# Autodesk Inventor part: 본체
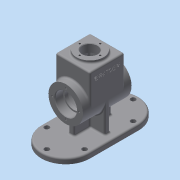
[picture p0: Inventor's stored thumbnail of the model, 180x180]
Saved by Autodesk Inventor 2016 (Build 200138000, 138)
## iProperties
Created: 2019-01
Part Number: 본체
Material: 알루미늄 6061
Document SubType Name: Modeling
Designer: mduedu
Density: 2.71 g/cm^3
Appearance: 기본값
Mass: 1057.72 g
Surface Area: 916.19 cm^2
Volume: 390.301 cm^3
Author: mduedu
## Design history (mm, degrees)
sketch "스케치1"
  geometry: C1 r 32 at (0, 0); 1 further point
  constraints: 1 centre point, 1 coincident
  dimensions: "d0" = 64 diameter of C1
extrude "돌출1" new body sketch "스케치1" stored distance "d1" = 90; taper "d2" = 0 deg
sketch "스케치2"
  geometry: L1 (0, 32)-(60, 32); L2 (60, 32)-(60, -32); L3 (60, -32)-(0, -32); L4 (0, -32)-(0, 32); C1 r 32 at (0, 0) reference; 2 further points
  constraints: 8 end point, 2 parallel, 1 coincident, 1 horizontal, 1 midpoint, 1 perpendicular, 1 tangent
  dimensions: "d5" = 60 distance between parallel lines of L4 L2
extrude "돌출2" join sketch "스케치2" stored distance "d7" = 64; taper "d8" = 0 deg
sketch "스케치3"
  geometry: C1 r 25 at (32, 32); 1 further point
  constraints: 1 centre point, 1 coincident
  dimensions: "d9" = 50 diameter of C1
extrude "돌출3" join sketch "스케치3" distance "d10" = 5; taper "d11" = 0 deg
sketch "스케치4"
  geometry: L1 (50, 25)-(0, 25); L2 (0, 25)-(0, -25); L3 (0, -25)-(50, -25); L4 (50, -25)-(50, 25); L5 (65, -25)-(65, 25) reference; A1 r 25 centre (0, 0) between (0, 25) and (0, -25); A2 r 25 centre (0, 0) between (0, -25) and (0, 25); 2 further points
  constraints: 8 end point, 4 point on circle, 2 centre point, 2 coincident, 2 parallel, 1 horizontal, 1 midpoint, 1 perpendicular, 1 tangent
  dimensions: "d12" = 50 diameter of A1; "d13" = 15 distance between parallel lines of L4 L5
extrude "돌출4" cut sketch "스케치4" stored distance "d14" = 48; taper "d15" = 0 deg
sketch "스케치5"
  geometry: C1 r 20 at (0, 0); 1 further point
  constraints: 1 centre point, 1 coincident
  dimensions: "d16" = 40 diameter of C1
extrude "돌출5" cut sketch "스케치5" distance "d17" = 15; taper "d18" = 0 deg
sketch "스케치6"
  geometry: C1 r 17 at (0, 0); 1 further point
  constraints: 1 centre point, 1 coincident
  dimensions: "d19" = 34 diameter of C1
extrude "돌출6" cut sketch "스케치6" stored distance "d20" = 15; taper "d21" = 0 deg
fillet "모깎기1" dims "d22" = 0.3
fillet "모깎기2" dims "d23" = 3
fillet "모깎기3" dims "d24" = 3
fillet "모깎기4" dims "d25" = 3
fillet "모깎기5" dims "d26" = 3
fillet "모깎기6" dims "d27" = 3
sketch "스케치7"
  geometry: C1 r 14 at (0, 0); 1 further point
  constraints: 1 centre point, 1 coincident
  dimensions: "d28" = 28 diameter of C1
extrude "돌출7" cut sketch "스케치7" stored distance "d29" = 15; taper "d30" = 0 deg
chamfer "모따기1" distance "d31" = 1; stored, may be unused: second distance "d32" = 2, angle "d33" = 45 deg
chamfer "모따기2" distance "d34" = 1; stored, may be unused: second distance "d35" = 2, angle "d36" = 45 deg
node "작업 평면1"
sketch "스케치8"
  geometry: L1 (45, 45)-(-45, 45); L2 (-45, 45)-(-45, -45); L3 (-45, -45)-(45, -45); L4 (45, -45)-(45, 45); L5 (45, 45)-(-45, -45); L6 (-45, 45)-(45, -45); A1 r 45 centre (45, 0) between (45, -45) and (45, 45); A2 r 45 centre (-45, 0) between (-45, 45) and (-45, -45); A3 r 45 centre (45, 0) between (0, 0) and (45, -45); A4 r 45 centre (45, 0) between (0, 0) and (0, 0); A5 r 45 centre (45, 0) between (45, 45) and (0, 0); A6 r 45 centre (-45, 0) between (0, 0) and (-45, 45); A7 r 45 centre (-45, 0) between (-45, -45) and (0, 0); 1 further point
  constraints: 14 point on circle, 12 end point, 7 centre point, 7 midpoint, 2 parallel, 1 horizontal, 1 perpendicular
  dimensions: "d99" = 90 distance between parallel lines of L1 L3; "d101" = 90 distance between parallel lines of L2 L4
extrude "돌출8" join sketch "스케치8" distance "d41" = 10; taper "d42" = 0 deg
sketch "스케치9"
  geometry: L1 (-35, 5)-(35, 5); L2 (35, 5)-(35, -5); L3 (35, -5)-(-35, -5); L4 (-35, -5)-(-35, 5); 3 further points
  constraints: 8 end point, 2 midpoint, 2 parallel, 1 horizontal, 1 horizontal alignment, 1 perpendicular, 1 vertical alignment
  dimensions: "d52" = 10 distance of L1.end L2.end; "d54" = 70 distance of L1.start L1.end
extrude "돌출9" join sketch "스케치9" stored distance "d50" = 10; taper "d51" = 0 deg
sketch "스케치10"
  geometry: L1 (0, -25)-(47, -25) reference; L2 (50, -22)-(50, -14) reference; L3 (50, -14)-(64, -14) reference; L4 (64, -14)-(65, -15) reference; L5 (65, -15)-(65, -25) reference; L6 (65, -25)-(63, -25) reference; L7 (60, -28)-(60, -29) reference; L8 (57, -32)-(0, -32) reference; L9 (-31.607, -5)-(-55, -5) reference; L10 (-55, -5)-(-55, -45) reference; L11 (-65, -45)-(-65, 45) reference; L12 (-55, 45)-(-55, 5) reference; L13 (-55, 5)-(-31.607, 5) reference; L14 (0, 32)-(57, 32) reference; L15 (60, 29)-(60, 28) reference; L16 (63, 25)-(65, 25) reference; L17 (65, 25)-(65, 15) reference; L18 (65, 15)-(64, 14) reference; L19 (64, 14)-(50, 14) reference; L20 (50, 14)-(50, 22) reference; L21 (47, 25)-(0, 25) reference; L22 (-55, -45)-(-65, -45) reference; L23 (-65, 45)-(-55, 45) reference; L24 (0, 32)-(-55, 32); A1 r 25 centre (0, 0) between (0, 25) and (0, -25) reference; A2 r 3 centre (47, -22) between (47, -25) and (50, -22) reference; A3 r 3 centre (63, -28) between (63, -25) and (60, -28) reference; A4 r 3 centre (57, -29) between (57, -32) and (60, -29) reference; A5 r 32 centre (0, 0) between (-31.607, -5) and (0, -32) reference; A6 r 32 centre (0, 0) between (0, 32) and (-31.607, 5) reference; A7 r 3 centre (57, 29) between (60, 29) and (57, 32) reference; A8 r 3 centre (63, 28) between (60, 28) and (63, 25) reference; A9 r 3 centre (47, 22) between (50, 22) and (47, 25) reference
  constraints: 2 end point, 1 perpendicular, 1 point on line, 1 tangent
feature "리브1" sketch "스케치10" dims "d57" = 1, "d58" = 10, "d59" = 0, "d60" = 0, "d61" = 1, "d62" = 1
fillet "모깎기7" dims "d63" = 3
fillet "모깎기11" dims "d102" = 3
fillet "모깎기8" dims "d64" = 3
sketch "스케치11"
  geometry: L1 (8, -29)-(8, -8) reference; L2 (-8, -8)-(-8, -29) reference; L3 (-32, -8)-(-8, -8) reference; L4 (-38, 2)-(-38, -2) reference; L5 (-8, 8)-(-32, 8) reference; L6 (-8, 29)-(-8, 8) reference; L7 (8, 8)-(8, 29) reference; L8 (32, 8)-(8, 8) reference; L9 (38, -2)-(38, 2) reference; L10 (8, -8)-(32, -8) reference; L11 (-2, -35)-(2, -35) reference; L12 (2, 35)-(-2, 35) reference; L13 (-45, -45)-(45, -45) reference; L14 (45, 45)-(-45, 45) reference; L15 (-45, -35)-(45, -35); L16 (45, 35)-(-45, 35); A1 r 6 centre (-32, -2) between (-38, -2) and (-32, -8) reference; A2 r 6 centre (-32, 2) between (-32, 8) and (-38, 2) reference; A3 r 6 centre (32, 2) between (38, 2) and (32, 8) reference; A4 r 6 centre (32, -2) between (32, -8) and (38, -2) reference; A5 r 6 centre (2, -29) between (2, -35) and (8, -29) reference; A6 r 6 centre (-2, -29) between (-8, -29) and (-2, -35) reference; A7 r 6 centre (-2, 29) between (-2, 35) and (-8, 29) reference; A8 r 6 centre (2, 29) between (8, 29) and (2, 35) reference; A9 r 45 centre (-45, 0) between (-45, 45) and (-45, -45) reference; A10 r 45 centre (45, 0) between (45, -45) and (45, 45) reference; A11 r 35 centre (-45, 0) between (-45, 35) and (-45, -35); A12 r 35 centre (45, 0) between (45, -35) and (45, 35); 7 further points
  constraints: 6 point on circle, 4 coincident, 4 end point, 2 centre point, 3 other
  dimensions: "d103" = 10 distance between parallel lines of L16 L14
hole "구멍1" sketch "스케치11" at (-45, 35), (-80, 0), (-45, -35), (45, -35), (80, 0), (45, 35) diameter "d66" = 9; stored, may be unused: countersink angle "d70" = 90 deg, drill point angle "d72" = 118 deg; dims "d67" = 6, "d68" = 4, "d69" = 2, "d71" = 8
fillet "모깎기10" dims "d73" = 3
sketch "스케치12"
  geometry: L1 (-3, 57)-(-3, 19.596) reference; 2 further points
  constraints: 1 other
  dimensions: "d74" = 32 distance from line of point (29, 45) L1; "d75" = 45 distance of point (29, 45) point (29, 0)
feature "엠보싱1" sketch "스케치12" dims "d12" = 50, "d13" = 15, "d76" = 0.5, "d77" = 0
sketch "스케치13"
  geometry: 4 further points
  constraints: 4 other
hole "구멍2" sketch "스케치13" at (-25, 0), (0, -25), (25, 0), (0, 25) diameter "d78" = 3.242; stored, may be unused: countersink angle "d82" = 90 deg, drill point angle "d84" = 120 deg; dims "d79" = 7, "d80" = 4, "d81" = 2, "d83" = 9
sketch "스케치14"
  geometry: 4 further points
  constraints: 4 other
hole "구멍3" sketch "스케치14" at (-25, 0), (0, -25), (25, 0), (0, 25) diameter "d85" = 3.242; stored, may be unused: countersink angle "d89" = 90 deg, drill point angle "d91" = 120 deg; dims "d86" = 7, "d87" = 4, "d88" = 2, "d90" = 9
sketch "스케치15"
  geometry: 4 further points
  constraints: 4 other
hole "구멍4" sketch "스케치15" at (0, -19), (19, 0), (0, 19), (-19, 0) diameter "d92" = 3.242; stored, may be unused: countersink angle "d96" = 90 deg, drill point angle "d98" = 120 deg; dims "d93" = 8, "d94" = 4, "d95" = 2, "d97" = 10
node "솔리드1"
mirror "대칭1"
mirror "대칭2"
node "투영된 루프1"
node "투영된 루프2"
node "절단 모서리 투영1"
node "절단 모서리 투영2"
other parameters: "d37" = -65
